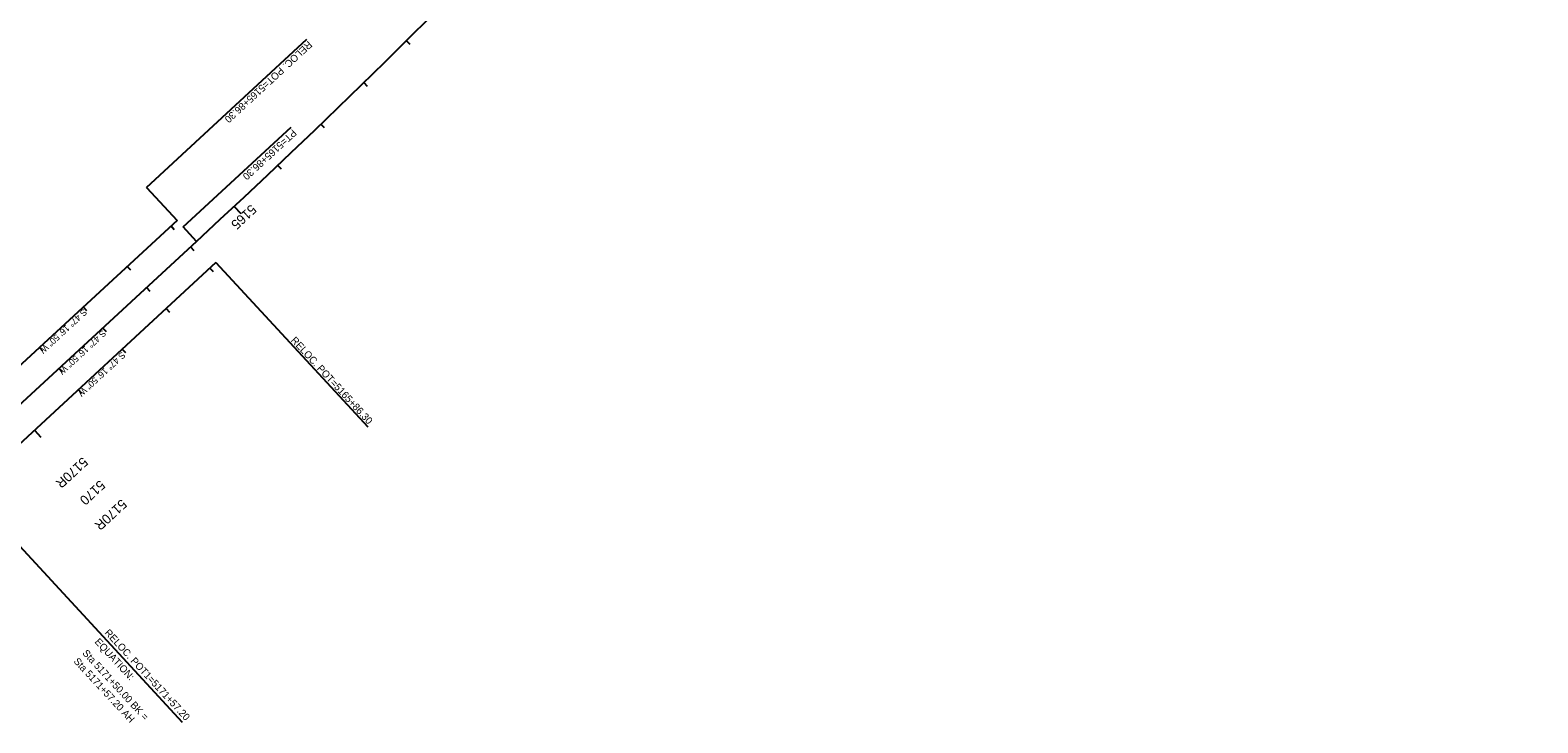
# Model space of a CAD drawing. Extents: x 2160876 to 2175625, y 601634 to 617693.
# Drawn here: x 2172375 to 2174900, y 613316 to 614476 of the extents above; entities that cross this region are included whole.
import ezdxf

# ---------------------------------------------------------------- set-up
doc = ezdxf.new("R2010")
doc.units = 0
for name, color, linetype in [('RD_HC_Cl', 7, 'Continuous'), ('RD_HC_CL_Rel', 7, 'Continuous'), ('RD_HC_Data', 7, 'Continuous'), ('RD_HC_Data_Rel', 7, 'Continuous'), ('RD_HC_Data_Tic', 7, 'Continuous'), ('RD_HC_Data_Tic_Rel', 7, 'Continuous'), ('RD_HC_TX_Rel_Sta50', 7, 'Continuous'), ('RD_HC_TX_Sta50', 7, 'Continuous')]:
    doc.layers.add(name, color=color, linetype=linetype)

msp = doc.modelspace()

# ---------------------------------------------------------------- linework, layer by layer
at = {"layer": 'RD_HC_Cl'}
msp.add_line((2172654, 614122.3), (2172239.9, 613739.9), dxfattribs=at)
msp.add_arc((2162936.5, 624645.9), 14323.9, 312.71947, 326.63611, dxfattribs=at)
at = {"layer": 'RD_HC_CL_Rel'}
for p, q in [((2172621.5, 614157.6), (2172207.3, 613775.1)), ((2172686.6, 614087), (2172272.5, 613704.6))]:
    msp.add_line(p, q, dxfattribs=at)
at = {"layer": 'RD_HC_Data'}
for p, q in [((2172631.6, 614146.5), (2172812.4, 614313.5)), ((2172654, 614122.3), (2172631.6, 614146.5))]:
    msp.add_line(p, q, dxfattribs=at)
at = {"layer": 'RD_HC_Data_Rel'}
for p, q in [((2172570.4, 614212.8), (2172838.9, 614460.8)), ((2172570.4, 614212.8), (2172621.5, 614157.6)), ((2172686.6, 614087), (2172940.7, 613811.9)), ((2172630.4, 613317), (2172272.5, 613704.6))]:
    msp.add_line(p, q, dxfattribs=at)
at = {"layer": 'RD_HC_Data_Tic'}
for p, q in [((2173005.6, 614458.2), (2173011.3, 614452.5)), ((2172934.3, 614388.2), (2172939.9, 614382.4)), ((2172862.4, 614318.6), (2172868, 614312.8)), ((2172790.1, 614249.6), (2172795.6, 614243.8)), ((2172717.3, 614181), (2172728.2, 614169.3)), ((2172644, 614113), (2172649.4, 614107.1)), ((2172570.5, 614045.2), (2172575.9, 614039.3)), ((2172497, 613977.3), (2172502.5, 613971.4)), ((2172423.6, 613909.5), (2172429, 613903.6))]:
    msp.add_line(p, q, dxfattribs=at)
at = {"layer": 'RD_HC_Data_Tic_Rel'}
for p, q in [((2172611.4, 614148.3), (2172616.8, 614142.4)), ((2172537.9, 614080.4), (2172543.4, 614074.5)), ((2172676.5, 614077.7), (2172682, 614071.9)), ((2172464.5, 614012.6), (2172469.9, 614006.7)), ((2172603.1, 614009.9), (2172608.5, 614004)), ((2172391, 613944.7), (2172396.4, 613938.9)), ((2172529.6, 613942.1), (2172535, 613936.2)), ((2172456.1, 613874.2), (2172461.5, 613868.3)), ((2172382.7, 613806.4), (2172393.5, 613794.6))]:
    msp.add_line(p, q, dxfattribs=at)

# ---------------------------------------------------------------- texts
at = {"layer": 'RD_HC_Data'}
for s, height, p in [('PT=5165+86.30', 12, (2172814.8, 614310.9)), ('S 47° 16\' 50" W', 10.8, (2172496.5, 613974.9))]:
    msp.add_text(s, height=height, rotation=222.7195, dxfattribs=at).set_placement(p)
at = {"layer": 'RD_HC_Data_Rel'}
for s, height, rotation, p in [('RELOC. POT=5165+86.30', 12, 222.7195, (2172840.9, 614458.6)), ('S 47° 16\' 50" W', 10.8, 222.7195, (2172464.6, 614010.3)), ('RELOC. POT=5165+86.30', 12, 312.7195, (2172811.2, 613956)), ('S 47° 16\' 50" W', 10.8, 222.7195, (2172528.8, 613938.4)), ('RELOC. POT1=5171+57.20', 12, 312.7195, (2172499.2, 613466.5)), ('EQUATION:', 12, 312.7195, (2172482.7, 613451.3)), ('Sta 5171+57.20 AH', 12, 312.7195, (2172447.4, 613418.7)), ('Sta 5171+50.00 BK = ', 12, 312.7195, (2172462.1, 613432.3))]:
    msp.add_text(s, height=height, rotation=rotation, dxfattribs=at).set_placement(p)
at = {"layer": 'RD_HC_TX_Rel_Sta50'}
for p in [(2172463.2, 613762.3), (2172528.3, 613691.8)]:
    msp.add_text('5170R', height=16, rotation=222.7195, dxfattribs=at).set_placement(p)
at = {"layer": 'RD_HC_TX_Sta50'}
for s, rotation, p in [('5165', 223.0647, (2172745.2, 614185.2)), ('5170', 222.7195, (2172492, 613723.6))]:
    msp.add_text(s, height=16, rotation=rotation, dxfattribs=at).set_placement(p)

doc.saveas('drawing.dxf')
